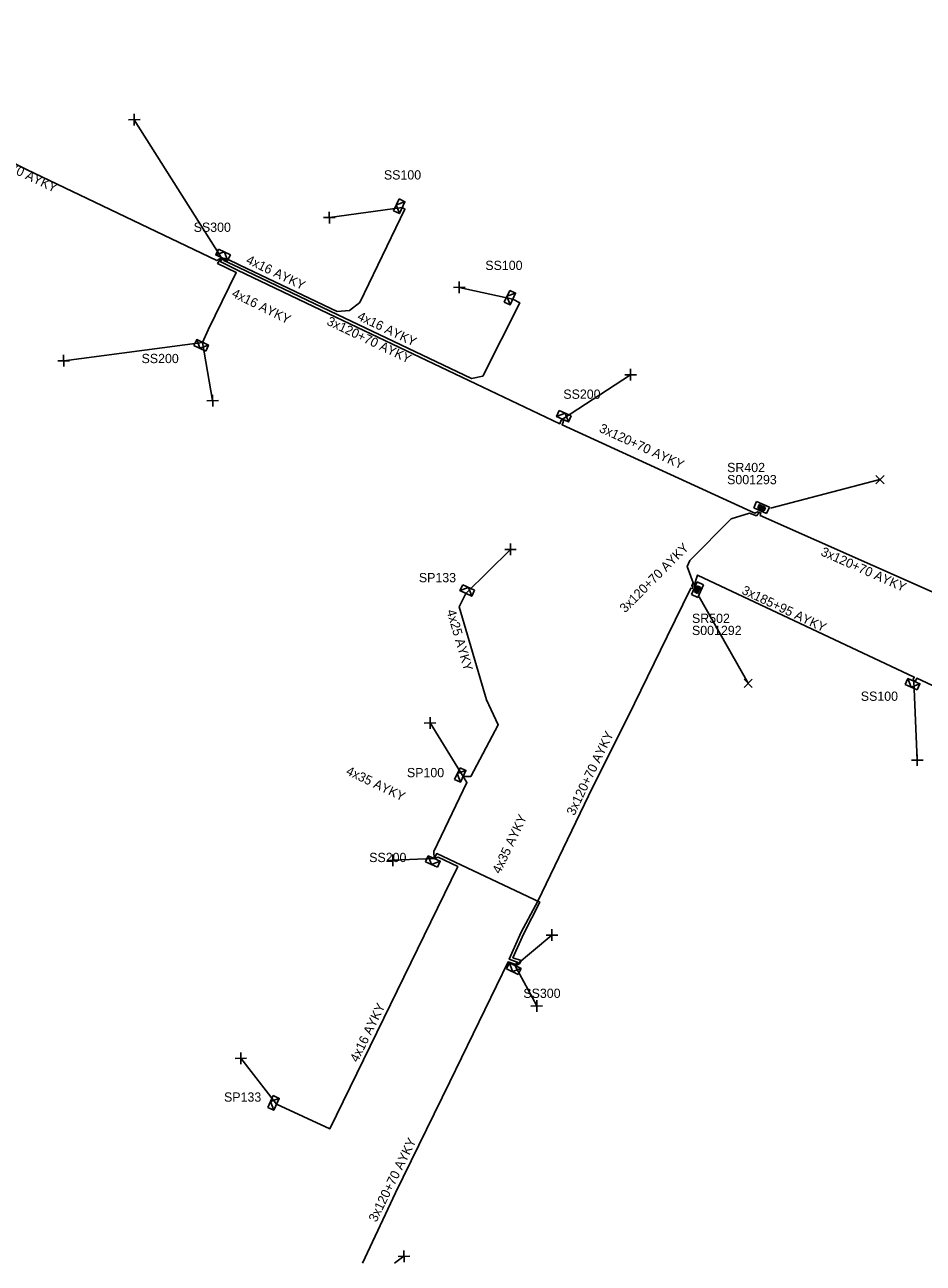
# Model space of a CAD drawing. Extents: x -762500 to -761285, y -1155006 to -1154135.
# Drawn here: x -762207.7 to -762111.4, y -1155000 to -1154867.1 of the extents above; entities that cross this region are included whole.
import ezdxf

# ---------------------------------------------------------------- set-up
doc = ezdxf.new("R2010")
doc.units = 0
for name, color, linetype in [('Vrstva 28', 7, 'Continuous'), ('Vrstva 29', 7, 'Continuous'), ('Vrstva 30', 7, 'Continuous'), ('Vrstva 31', 7, 'Continuous'), ('Vrstva 33', 7, 'Continuous'), ('Vrstva 34', 7, 'Continuous'), ('Vrstva 5', 7, 'Continuous'), ('Vrstva 59', 7, 'Continuous'), ('Vrstva 6', 7, 'Continuous')]:
    doc.layers.add(name, color=color, linetype=linetype)

msp = doc.modelspace()

# ---------------------------------------------------------------- linework, layer by layer
at = {"layer": 'Vrstva 28'}
for points in [[(-762129.224, -1154918.242), (-762129.529, -1154918.927)], [(-762127.853, -1154918.852), (-762129.224, -1154918.242)], [(-762128.95, -1154918.571), (-762129.104, -1154918.916)], [(-762128.926, -1154918.633), (-762129.041, -1154918.892)], [(-762129.041, -1154918.892), (-762128.448, -1154919.156)], [(-762128.902, -1154918.696), (-762128.979, -1154918.868)], [(-762128.979, -1154918.868), (-762128.472, -1154919.094)], [(-762128.27, -1154918.874), (-762128.95, -1154918.571)], [(-762128.332, -1154918.897), (-762128.926, -1154918.633)], [(-762128.878, -1154918.758), (-762128.917, -1154918.844)], [(-762128.917, -1154918.844), (-762128.496, -1154919.032)], [(-762128.395, -1154918.921), (-762128.902, -1154918.696)], [(-762128.457, -1154918.945), (-762128.878, -1154918.758)], [(-762128.514, -1154918.972), (-762128.859, -1154918.818)], [(-762128.448, -1154919.156), (-762128.332, -1154918.897)], [(-762128.424, -1154919.219), (-762128.27, -1154918.874)], [(-762128.158, -1154919.537), (-762127.853, -1154918.852)], [(-762129.529, -1154918.927), (-762128.158, -1154919.537)], [(-762129.104, -1154918.916), (-762128.424, -1154919.219)], [(-762128.496, -1154919.032), (-762128.457, -1154918.945)], [(-762128.472, -1154919.094), (-762128.395, -1154918.921)], [(-762135.595, -1154926.846), (-762136.229, -1154928.206)], [(-762134.915, -1154927.163), (-762135.595, -1154926.846)], [(-762136.229, -1154928.206), (-762135.549, -1154928.523)], [(-762135.591, -1154927.272), (-762135.906, -1154927.946)], [(-762135.906, -1154927.946), (-762135.563, -1154928.106)], [(-762135.568, -1154927.334), (-762135.843, -1154927.923)], [(-762135.843, -1154927.923), (-762135.586, -1154928.043)], [(-762135.546, -1154927.397), (-762135.78, -1154927.9)], [(-762135.78, -1154927.9), (-762135.609, -1154927.98)], [(-762135.523, -1154927.46), (-762135.717, -1154927.878)], [(-762135.717, -1154927.878), (-762135.632, -1154927.917)], [(-762135.657, -1154927.86), (-762135.497, -1154927.518)], [(-762135.632, -1154927.917), (-762135.437, -1154927.5)], [(-762135.609, -1154927.98), (-762135.374, -1154927.477)], [(-762135.249, -1154927.431), (-762135.591, -1154927.272)], [(-762135.586, -1154928.043), (-762135.312, -1154927.454)], [(-762135.312, -1154927.454), (-762135.568, -1154927.334)], [(-762135.563, -1154928.106), (-762135.249, -1154927.431)], [(-762135.549, -1154928.523), (-762134.915, -1154927.163)], [(-762135.374, -1154927.477), (-762135.546, -1154927.397)], [(-762135.437, -1154927.5), (-762135.523, -1154927.46)]]:
    msp.add_lwpolyline(points, dxfattribs=at)
at = {"layer": 'Vrstva 31'}
for points in [[(-762167.588, -1154885.756), (-762168.179, -1154887.025)], [(-762167.588, -1154885.756), (-762166.953, -1154886.052), (-762167.545, -1154887.321), (-762168.179, -1154887.025)], [(-762167.883, -1154886.391), (-762166.953, -1154886.052)], [(-762167.883, -1154886.391), (-762167.545, -1154887.321)], [(-762185.681, -1154891.749), (-762185.988, -1154892.378), (-762187.246, -1154891.764), (-762186.94, -1154891.135)], [(-762186.31, -1154891.442), (-762187.246, -1154891.764)], [(-762185.681, -1154891.749), (-762186.94, -1154891.135)], [(-762186.31, -1154891.442), (-762185.988, -1154892.378)], [(-762155.718, -1154895.567), (-762156.309, -1154896.836)], [(-762155.718, -1154895.567), (-762155.083, -1154895.863), (-762155.675, -1154897.132), (-762156.309, -1154896.836)], [(-762156.013, -1154896.201), (-762155.083, -1154895.863)], [(-762156.013, -1154896.201), (-762155.675, -1154897.132)], [(-762189.593, -1154901.488), (-762189.297, -1154900.854), (-762188.029, -1154901.445), (-762188.324, -1154902.08)], [(-762189.593, -1154901.488), (-762188.324, -1154902.08)], [(-762188.959, -1154901.784), (-762189.297, -1154900.854)], [(-762188.959, -1154901.784), (-762188.029, -1154901.445)], [(-762149.113, -1154909.046), (-762149.398, -1154909.685), (-762150.677, -1154909.116), (-762150.392, -1154908.476)], [(-762149.753, -1154908.761), (-762150.677, -1154909.116)], [(-762149.113, -1154909.046), (-762150.392, -1154908.476)], [(-762149.753, -1154908.761), (-762149.398, -1154909.685)], [(-762159.487, -1154927.762), (-762159.783, -1154928.396), (-762161.052, -1154927.805), (-762160.756, -1154927.17)], [(-762160.121, -1154927.466), (-762161.052, -1154927.805)], [(-762159.487, -1154927.762), (-762160.756, -1154927.17)], [(-762160.121, -1154927.466), (-762159.783, -1154928.396)], [(-762113.277, -1154937.873), (-762112.992, -1154937.234), (-762111.713, -1154937.803), (-762111.998, -1154938.443)], [(-762112.638, -1154938.158), (-762112.992, -1154937.234)], [(-762113.277, -1154937.873), (-762111.998, -1154938.443)], [(-762112.638, -1154938.158), (-762111.713, -1154937.803)], [(-762161.038, -1154946.807), (-762161.63, -1154948.076)], [(-762161.038, -1154946.807), (-762160.404, -1154947.103), (-762160.995, -1154948.371), (-762161.63, -1154948.076)], [(-762161.334, -1154947.441), (-762160.404, -1154947.103)], [(-762161.334, -1154947.441), (-762160.995, -1154948.371)], [(-762164.737, -1154956.914), (-762164.452, -1154956.274), (-762163.173, -1154956.844), (-762163.458, -1154957.483)], [(-762164.737, -1154956.914), (-762163.458, -1154957.483)], [(-762164.098, -1154957.198), (-762164.452, -1154956.274)], [(-762164.098, -1154957.198), (-762163.173, -1154956.844)], [(-762156.058, -1154968.391), (-762155.751, -1154967.762), (-762154.493, -1154968.375), (-762154.8, -1154969.005)], [(-762155.429, -1154968.698), (-762155.751, -1154967.762)], [(-762156.058, -1154968.391), (-762154.8, -1154969.005)], [(-762155.429, -1154968.698), (-762154.493, -1154968.375)], [(-762181.078, -1154982.007), (-762181.669, -1154983.275)], [(-762181.078, -1154982.007), (-762180.443, -1154982.302), (-762181.035, -1154983.571), (-762181.669, -1154983.275)], [(-762181.373, -1154982.641), (-762180.443, -1154982.302)], [(-762181.373, -1154982.641), (-762181.035, -1154983.571)]]:
    msp.add_lwpolyline(points, dxfattribs=at)
at = {"layer": 'Vrstva 34'}
for points in [[(-762196.625, -1154877.261), (-762195.375, -1154877.239)], [(-762195.989, -1154877.875), (-762196.011, -1154876.625)], [(-762175.685, -1154887.761), (-762174.435, -1154887.739)], [(-762175.049, -1154888.375), (-762175.071, -1154887.125)], [(-762161.119, -1154895.875), (-762161.141, -1154894.625)], [(-762161.755, -1154895.261), (-762160.505, -1154895.239)], [(-762203.549, -1154903.755), (-762203.571, -1154902.505)], [(-762204.185, -1154903.141), (-762202.935, -1154903.119)], [(-762142.739, -1154905.255), (-762142.761, -1154904.005)], [(-762143.375, -1154904.641), (-762142.125, -1154904.619)], [(-762187.579, -1154908.025), (-762187.601, -1154906.775)], [(-762188.215, -1154907.411), (-762186.965, -1154907.389)], [(-762116.442, -1154915.438), (-762115.558, -1154916.322)], [(-762116.442, -1154916.322), (-762115.558, -1154915.438)], [(-762155.619, -1154924.005), (-762155.641, -1154922.755)], [(-762156.255, -1154923.391), (-762155.005, -1154923.369)], [(-762130.572, -1154937.308), (-762129.688, -1154938.192)], [(-762130.572, -1154938.192), (-762129.688, -1154937.308)], [(-762164.239, -1154942.625), (-762164.261, -1154941.375)], [(-762164.875, -1154942.011), (-762163.625, -1154941.989)], [(-762111.989, -1154946.625), (-762112.011, -1154945.375)], [(-762112.625, -1154946.011), (-762111.375, -1154945.989)], [(-762168.239, -1154957.375), (-762168.261, -1154956.125)], [(-762168.875, -1154956.761), (-762167.625, -1154956.739)], [(-762151.815, -1154964.791), (-762150.565, -1154964.769)], [(-762151.179, -1154965.405), (-762151.201, -1154964.155)], [(-762152.799, -1154973.005), (-762152.821, -1154971.755)], [(-762153.435, -1154972.391), (-762152.185, -1154972.369)], [(-762184.549, -1154978.625), (-762184.571, -1154977.375)], [(-762185.185, -1154978.011), (-762183.935, -1154977.989)], [(-762167.049, -1154999.875), (-762167.071, -1154998.625)], [(-762167.685, -1154999.261), (-762166.435, -1154999.239)]]:
    msp.add_lwpolyline(points, dxfattribs=at)
at = {"layer": 'Vrstva 5'}
for points in [[(-762221.78, -1154867.06), (-762222.05, -1154867.23), (-762222.44, -1154868.44), (-762222.94, -1154872.29), (-762223.69, -1154874.34), (-762223.76, -1154874.47), (-762214.19, -1154879.24), (-762207.57, -1154882.59), (-762187.13, -1154892.38), (-762186.62, -1154892.07)], [(-762186.62, -1154892.07), (-762186.07, -1154892.18), (-762184.67, -1154892.86), (-762174.21, -1154897.84), (-762172.9, -1154897.72), (-762171.8, -1154896.89), (-762166.96, -1154886.85), (-762167.25, -1154886.69)], [(-762186.62, -1154892.07), (-762187.05, -1154892.68), (-762185.05, -1154893.67), (-762188.08, -1154899.82), (-762188.66, -1154901.15)], [(-762186.62, -1154892.07), (-762186.71, -1154892.52), (-762184.93, -1154893.4), (-762174.36, -1154898.44), (-762150.34, -1154909.88), (-762150.21, -1154909.51), (-762150.04, -1154909.4), (-762149.96, -1154909.62), (-762150.1, -1154909.99), (-762129.41, -1154919.47), (-762129.01, -1154919.3)], [(-762186.62, -1154892.07), (-762186.37, -1154892.35), (-762184.79, -1154893.13), (-762174.23, -1154898.16), (-762159.8, -1154905.04), (-762158.61, -1154904.77), (-762154.64, -1154896.9), (-762155.38, -1154896.5)], [(-762136.03, -1154927.47), (-762136.18, -1154927.27), (-762136.03, -1154926.95), (-762136.69, -1154925.2), (-762136.4, -1154924.56), (-762131.95, -1154920.09), (-762130, -1154919.48), (-762129.24, -1154919.76), (-762128.89, -1154919.35)], [(-762128.78, -1154919.4), (-762128.84, -1154919.72), (-762110.73, -1154927.77), (-762105.11, -1154930.3), (-762103.87, -1154931.08), (-762103.27, -1154930.75), (-762102.67, -1154930.54)], [(-762135.97, -1154927.36), (-762135.55, -1154926.14), (-762112.32, -1154937.09), (-762112.43, -1154937.34), (-762112.35, -1154937.52), (-762112.16, -1154937.46), (-762112.05, -1154937.21), (-762087.8, -1154948.55), (-762087.93, -1154948.83), (-762087.85, -1154949.03), (-762087.66, -1154948.97), (-762087.52, -1154948.67), (-762056.95, -1154963.18), (-762056.96, -1154963.64)], [(-762160.7, -1154947.74), (-762159.89, -1154947.77), (-762156.94, -1154942.22), (-762158.22, -1154939.52), (-762161.15, -1154929.54), (-762160.42, -1154928.1)], [(-762155.12, -1154968.07), (-762154.91, -1154967.68), (-762155.77, -1154967.37), (-762154.47, -1154964.47), (-762152.7, -1154961.14), (-762146.8, -1154948.85), (-762143.04, -1154941.39), (-762138.81, -1154932.71), (-762136.3, -1154927.55), (-762136.08, -1154927.59)], [(-762163.81, -1154956.56), (-762163.86, -1154955.81), (-762160.3, -1154948.38), (-762160.7, -1154947.74)], [(-762155.12, -1154968.07), (-762154.63, -1154967.81), (-762154.48, -1154967.52), (-762155.37, -1154967.2), (-762154.2, -1154964.6), (-762152.49, -1154961.24), (-762163.54, -1154956.02), (-762163.81, -1154956.56)], [(-762163.81, -1154956.56), (-762163.4, -1154956.42), (-762161.29, -1154957.42), (-762175, -1154985.57), (-762180.74, -1154982.93)], [(-762171.52, -1155000), (-762167.97, -1154992.44), (-762162.12, -1154980.52), (-762155.88, -1154967.65), (-762155.16, -1154967.91), (-762155.12, -1154968.07)]]:
    msp.add_lwpolyline(points, dxfattribs=at)
at = {"layer": 'Vrstva 59'}
for points in [[(-762186.62, -1154892.07), (-762196, -1154877.25)], [(-762167.25, -1154886.69), (-762175.06, -1154887.75)], [(-762155.38, -1154896.5), (-762161.13, -1154895.25)], [(-762188.66, -1154901.15), (-762203.56, -1154903.13)], [(-762188.66, -1154901.15), (-762187.59, -1154907.4)], [(-762150.04, -1154909.4), (-762142.75, -1154904.63)], [(-762127.74, -1154918.94), (-762116, -1154915.88)], [(-762160.42, -1154928.1), (-762155.63, -1154923.38)], [(-762135.39, -1154928.46), (-762130.13, -1154937.75)], [(-762112.35, -1154937.52), (-762112, -1154946)], [(-762160.7, -1154947.74), (-762164.25, -1154942)], [(-762163.81, -1154956.56), (-762168.25, -1154956.75)], [(-762155.12, -1154968.07), (-762151.19, -1154964.78)], [(-762155.12, -1154968.07), (-762152.81, -1154972.38)], [(-762180.74, -1154982.94), (-762184.56, -1154978)], [(-762168.08, -1155000), (-762167.06, -1154999.25)]]:
    msp.add_lwpolyline(points, dxfattribs=at)

# ---------------------------------------------------------------- texts
at = {"layer": 'Vrstva 29'}
for s, p in [('S001293', (-762132.39, -1154916.38)), ('S001292', (-762136.16, -1154932.57))]:
    msp.add_text(s, height=0.9943, dxfattribs=at).set_placement(p)
at = {"layer": 'Vrstva 30'}
for s, p in [('SR402', (-762132.39, -1154915.08)), ('SR502', (-762136.16, -1154931.27))]:
    msp.add_text(s, height=0.9943, dxfattribs=at).set_placement(p)
at = {"layer": 'Vrstva 33'}
for s, p in [('SS100', (-762169.21, -1154883.67)), ('SS300', (-762189.62, -1154889.29)), ('SS100', (-762158.33, -1154893.38)), ('SS200', (-762195.21, -1154903.38)), ('SS200', (-762149.96, -1154907.21)), ('SP133', (-762165.46, -1154926.9)), ('SS100', (-762118.05, -1154939.63)), ('SP100', (-762166.74, -1154947.83)), ('SS200', (-762170.79, -1154956.94)), ('SS300', (-762154.25, -1154971.52)), ('SP133', (-762186.36, -1154982.66))]:
    msp.add_text(s, height=0.9943, dxfattribs=at).set_placement(p)
at = {"layer": 'Vrstva 6'}
for s, height, rotation, p in [('3x120+70 AYKY', 0.99429, 334.42456, (-762213.39, -1154880.87)), ('4x16 AYKY', 0.9943, 334.50966, (-762184.08, -1154892.63)), ('4x16 AYKY', 0.9943, 333.77512, (-762185.62, -1154896.21)), ('3x120+70 AYKY', 0.99428, 334.51175, (-762175.42, -1154899.22)), ('4x16 AYKY', 0.9943, 334.51231, (-762172.15, -1154898.68)), ('3x120+70 AYKY', 0.99429, 335.36852, (-762146.2, -1154910.72)), ('3x120+70 AYKY', 0.99429, 45.12847, (-762143.33, -1154930.24)), ('3x120+70 AYKY', 0.99429, 336.04368, (-762122.42, -1154923.98)), ('3x185+95 AYKY', 0.99429, 334.76907, (-762130.91, -1154928.1)), ('4x25 AYKY', 0.9943, 286.35691, (-762162.5, -1154929.98)), ('3x120+70 AYKY', 0.99428, 64.35596, (-762148.78, -1154952.02)), ('4x35 AYKY', 0.9943, 334.43676, (-762173.36, -1154947.49)), ('4x35 AYKY', 0.9943, 64.74772, (-762156.74, -1154958.27)), ('4x16 AYKY', 0.9943, 64.03712, (-762172.02, -1154978.5)), ('3x120+70 AYKY', 0.99429, 63.8595, (-762170.02, -1154995.66))]:
    msp.add_text(s, height=height, rotation=rotation, dxfattribs=at).set_placement(p)

doc.saveas('drawing.dxf')
